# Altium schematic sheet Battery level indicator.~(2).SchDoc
size A3; SheetNumber: 3; SheetTotal: 3
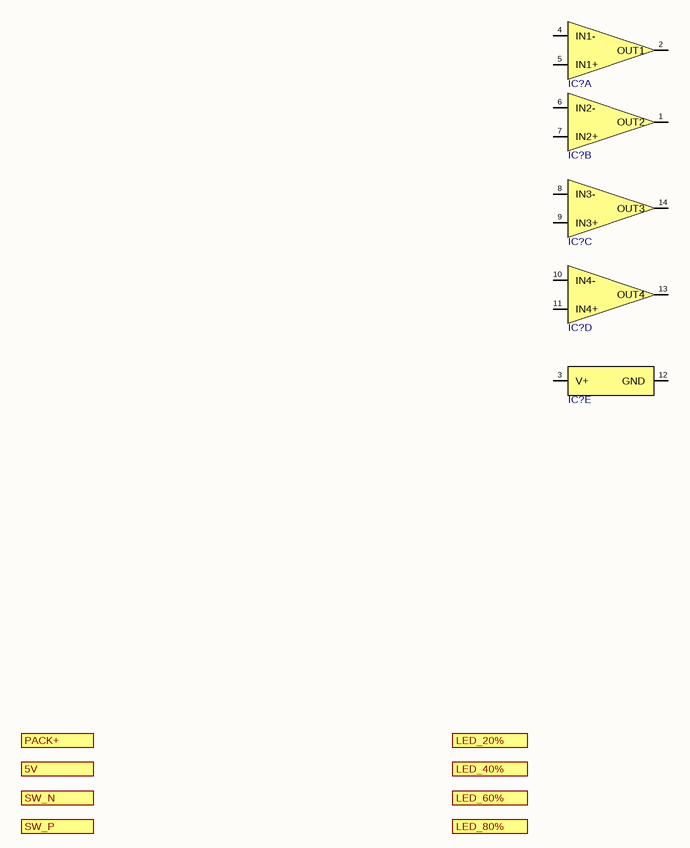
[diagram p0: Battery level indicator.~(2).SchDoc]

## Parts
(Parts that share a designator on the sheet are numbered #1, #2 ... from top to bottom, then left to right.)
IC?#1  LM339LVPWR  [TSSOP-14]  (value not drawn)  (part A of 5)
IC?#2  LM339LVPWR  [TSSOP-14]  (value not drawn)  (part B of 5)
IC?#3  LM339LVPWR  [TSSOP-14]  (value not drawn)  (part C of 5)
IC?#4  LM339LVPWR  [TSSOP-14]  (value not drawn)  (part D of 5)
IC?#5  LM339LVPWR  [TSSOP-14]  (value not drawn)  (part E of 5)

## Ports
5V (see Arhitecture[7C]), LED_20% (see Arhitecture[8C]), LED_40% (see Arhitecture[8C]), LED_60% (see Arhitecture[8C]), LED_80% (see Arhitecture[8D]), PACK+ (see Arhitecture[7C], Charger[8A]), SW_N (see Arhitecture[7D]), SW_P (see Arhitecture[7C])

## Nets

Not connected (* = marked no-connect by the designer): IC?#1 2(OUT1) 4(IN1-) 5(IN1+); IC?#2 1(OUT2) 6(IN2-) 7(IN2+); IC?#3 8(IN3-) 9(IN3+) 14(OUT3); IC?#4 10(IN4-) 11(IN4+) 13(OUT4); IC?#5 3(V+) 12(GND)

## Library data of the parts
IC?#1-IC?#5 = LM339LVPWR: Comparator Quad 1.65~5.5V TSSOP-14; Manufacturer: Texas Instruments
